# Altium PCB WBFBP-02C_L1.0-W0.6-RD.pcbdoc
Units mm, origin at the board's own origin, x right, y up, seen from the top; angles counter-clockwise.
Board outline 14.64 x 13.5 mm, 2 copper layers (Top Layer, Bottom Layer), stack 0 mm thick; 1 components, 0 nets, 2 pads, 0 vias.
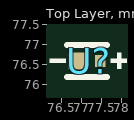
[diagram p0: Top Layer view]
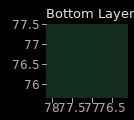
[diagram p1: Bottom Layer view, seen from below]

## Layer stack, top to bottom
Top Layer: signal copper (thickness not stored)
Bottom Layer: signal copper (thickness not stored)

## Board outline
84.485,69.85 69.85,69.85 69.85,83.35 84.485,83.35

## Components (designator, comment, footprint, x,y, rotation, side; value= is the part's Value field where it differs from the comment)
U? "" WBFBP-02C_L1.0-W0.6-RD 77.18,76.6 r0 top

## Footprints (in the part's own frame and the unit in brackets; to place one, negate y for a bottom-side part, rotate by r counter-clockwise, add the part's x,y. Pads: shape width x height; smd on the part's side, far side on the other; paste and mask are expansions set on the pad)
WBFBP-02C_L1.0-W0.6-RD [mm]
  rect 0.27x0.3 smd: 1(0.29,0)
  rect 0.43x0.42 smd: 2(-0.29,0)
  silkscreen extent -0.98,-0.4 0.95,0.4

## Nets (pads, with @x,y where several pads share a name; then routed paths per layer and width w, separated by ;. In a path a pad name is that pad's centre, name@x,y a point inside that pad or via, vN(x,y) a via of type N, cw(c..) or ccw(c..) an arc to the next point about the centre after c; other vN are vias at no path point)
pads on no net: U?.1 U?.2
